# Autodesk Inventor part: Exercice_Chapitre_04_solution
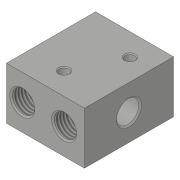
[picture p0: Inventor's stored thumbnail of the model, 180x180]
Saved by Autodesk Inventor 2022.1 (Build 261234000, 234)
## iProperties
RuleStatus: InUse
Created: 2018-06
Part Number: Exercice_Chapitre_04_solution
Material: Générique
Document SubType Name: Modeling
Designer: Fabian Perrée
Density: 1 g/cm^3
Appearance: Gris clair
Mass: 46.4551 g
Surface Area: 130.425 cm^2
Volume: 46.4551 cm^3
Author: Fabian Perrée
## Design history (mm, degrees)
sketch "Esquisse1"
  geometry: L1 (-21, 24)-(21, 24); L2 (21, 24)-(21, -24); L3 (21, -24)-(-21, -24); L4 (-21, -24)-(-21, 24); L5 (-21, 24)-(21, -24); L6 (21, 24)-(-21, -24); 1 further point
  constraints: 12 end point, 2 midpoint, 2 parallel, 1 horizontal, 1 perpendicular
  dimensions: "d0" = 48 distance of L1.end L2.end; "d1" = 42 distance of L2.end L3.end
extrude "Extrusion1" new body sketch "Esquisse1" stored distance "d2" = 28; taper "d3" = 0 deg
sketch "Esquisse2"
  geometry: L1 (21, 24)-(21, -24) reference; L2 (21, 0)-(-21, 0); L3 (-21, 24)-(21, 24) reference; L4 (21, -24)-(-21, -24) reference; L5 (0, -24)-(0, 24); L6 (12.5, 24)-(12.5, 0); L7 (18.5, 24)-(18.5, 13); L8 (18.5, 13)-(17.75, 13); L9 (16.25, 11.5)-(16.25, 10); L10 (16.25, 10)-(14.5, 10); L11 (14.5, 10)-(14.5, 0); L12 (21, -6)-(8.5, -6); L13 (8.5, -6)-(8.5, -5.25); L14 (8.5, -5.25)-(5.5, -5.25); L15 (5.5, -5.25)-(5.5, -2.5); L16 (5.5, -2.5)-(0.5, -2.5); L17 (0.5, -2.5)-(0.5, -2); L18 (0.5, -2)-(-0.5, -2); L19 (-0.5, -2)-(-0.5, -6); L20 (-0.5, -6)-(-21, -6); L21 (-21, -24)-(-21, 24) reference; L22 (21, -6)-(21, 0); L23 (-21, -6)-(-21, 0); A1 r 1.5 centre (17.75, 11.5) between (17.75, 13) and (16.25, 11.5); 2 further points
  constraints: 38 end point, 12 perpendicular, 8 point on line, 3 horizontal, 3 midpoint, 2 point on circle, 2 tangent, 1 centre point, 1 collinear, 1 parallel, 1 vertical
  dimensions: "d6" = 12 diameter of L7 L6; "d7" = 8.5 distance between parallel lines of L1 L6; "d8" = 7.5 diameter of L9 L6; "d9" = 4 diameter of L11 L6; "d10" = 11 distance of L7.start L7.end; "d11" = 3 distance of point (16.25, 13) L9.end; "d12" = 1.5 radius of A1; "d19" = 12 diameter of L12 L2; "d20" = 10.5 diameter of L14 L2; "d21" = 5 diameter of L16 L2; "d22" = 4 diameter of L18 L2; "d23" = 1 distance of L17.end L18.end; "d24" = 12 diameter of L20 L2; "d25" = 12.5 distance of L12.start L12.end; "d26" = 15.5 distance between parallel lines of L15 L1; "d27" = 20.5 distance of L19.end L20.end
revolve "Révolution1" stored, may be unused: angle "d35" = 90 deg
sketch "Esquisse3"
  geometry: C1 r 6 at (8.5, -14) reference; 2 further points
  constraints: 1 horizontal alignment
  dimensions: "d36" = 22.5 distance of C1.centre point (31, -14)
sketch "Esquisse4"
  geometry: L1 (42, 0)-(42, -28) reference; 2 further points
  constraints: 1 horizontal alignment
  dimensions: "d37" = 18 distance from line of L1 point (24, -14)
feature "Filetage1" dims "d42" = 10, "d43" = 0
feature "Réseau basé sur une esquisse1"
feature "Réseau basé sur une esquisse2"
revolve "Révolution2" stored, may be unused: angle "d38" = 90 deg
feature "Filetage2" dims "d47" = 10, "d48" = 0
sketch "Esquisse5"
  geometry: C1 r 2.5 at (-24, 14) reference; C2 r 2 at (-24, 14) reference; 2 further points
  dimensions: "d49" = 19 horizontal distance of C1.centre point (-43, 5); "d50" = 9 vertical distance of C2.centre point (-43, 5); "d51" = 19 horizontal distance of point (-5, 23) C1.centre; "d52" = 9 vertical distance of point (-5, 23) C1.centre
hole "Perçage1" sketch "Esquisse5" at (-43, 5), (-5, 23) diameter "d53" = 4.134; stored, may be unused: countersink angle "d57" = 90 deg, drill point angle "d59" = 118 deg; dims "d54" = 10, "d55" = 4, "d56" = 2, "d58" = 12.5
sketch "Esquisse6"
  geometry: L1 (21, 24)-(-21, 24) reference; L2 (21, -24)-(21, 24) reference; L3 (-21, 24)-(-21, -24) reference; L4 (-21, -24)-(21, -24) reference; 3 further points
  dimensions: "d63" = 12 distance from line of L1 point (9.5, 12); "d65" = 19 distance from line of L3 point (-2, -12); "d66" = 12 distance from line of L4 point (-2, -12); "d74" = 30.5 distance from line of L3 point (9.5, 12)
hole "Perçage2" sketch "Esquisse6" at (9.5, 12), (-2, -12) diameter "d67" = 5; stored, may be unused: countersink angle "d71" = 90 deg, drill point angle "d73" = 118 deg; dims "d68" = 10, "d69" = 6, "d70" = 2, "d72" = 12.5
chamfer "Chanfrein4" distance "d75" = 0.75; stored, may be unused: second distance "d76" = 2, angle "d77" = 45 deg
node "Solide1"
